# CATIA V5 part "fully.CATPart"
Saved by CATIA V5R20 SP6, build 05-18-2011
Part number: Gear_24_4H
Material "Gold Metal": density 7860 kg/m3, Young's modulus 2e+11 Pa, Poisson ratio 0.266
Bounding box of the stored display mesh (mm): x -23.5 to 23.5, y -125.239 to 125.239, z -125.245 to 125.245
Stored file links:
  E:\#01 CATIA Lecture Materials\#06 DMU\#11 DMU Page01 KIN EX11\fully.CATPart
  E:\06년 공학과제\CATIA File\Part2.CATPart
  C:\Program Files\Dassault Systemes\B20\win_b64\startup\materials\Catalog.CATMaterial
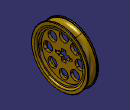
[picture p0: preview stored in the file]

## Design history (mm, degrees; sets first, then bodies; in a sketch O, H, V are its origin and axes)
Body1 (main body), material "Gold Metal"
  Sketch1, origin (0, 0, 0), H (0, 1, 0), V (0, 0, 1), geometry linked from another document
  Sketch2, origin (0, 0, 0), H (0, 1, 0), V (0, 0, 1), geometry linked from another document
  Sketch3, origin (0, 0, 0), H (0, -1, 0), V (0, 0, 1), geometry linked from another document
  Pad1: profile Sketch2, direction (1, 0, 0), length 18.5, mirrored extent
  Sketch4 on start face of Pad1, origin (-18.5, 0, 0), H (0, -1, 0), V (0, 0, 1)
    circle A1 centre (0, 0) radius 97.5
    radius A1 = 97.5
  Pocket1: profile Sketch4, direction (1, 0, 0), length 13
  Mirror1: of Pocket1, about yz-plane
  Sketch5 on end face of Pocket1, origin (-5.5, 0, 0), H (0, -1, 0), V (0, 0, 1)
  Pocket2: profile Sketch1, direction (-1, 0, 0), through (limit type 3), opposite side through (limit type 3)
  Body2
    Sketch6 on start face of Pad1, origin (-18.5, 0, 0), H (0, -1, 0), V (0, 0, 1)
      construction circle A1 centre (0, 0) radius 90
      construction circle A2 centre (0, 0) radius 50
      circle A3 centre (49.4975, 49.4975) radius 20
      axis line L1 (49.4975, 49.4975) -> (0, 0)
      radius A1 = 90
      radius A2 = 50
      angle L1 V = 45
      tangency: A3 A1, A3 A2
  Add1: tool Body2
  Pocket3: profile Sketch6, direction (-1, 0, 0), through (limit type 3)
  CircPattern1: of Pocket3, instances 8, angular step 45 {= 360.0*1 deg/CircPattern1.AngularNumber}, axis from face of Pad1
  Sketch7 on end face of Pocket1, origin (-5.5, 0, 0), H (0, -1, 0), V (0, 0, 1)
    line L1 (-36, 5) -> (36, 5)
    line L2 (36, 5) -> (36, -5)
    line L3 (36, -5) -> (-36, -5)
    line L4 (-36, -5) -> (-36, 5)
    distance V L2 = 36
    length L2 = 10
    horizontal: L1 H, L3 H
    vertical: L2 V, L4 V
    symmetry: L1 L3 H, L4 L2 V
  Pocket4: profile Sketch7, direction (1, 0, 0), through (limit type 3)
  Sketch8 on zx-plane, origin (0, 0, 0), H (-1, 0, 0), V (0, 0, 1)
    line L1 (-23.5, -111.2454) -> (-23.5, -123.2454)
    line L2 (-21.5, -125.2454) -> (-19.7031, -125.2454)
    line L3 (-17.7031, -123.2454) -> (-17.7031, -120.2807)
    point P1 (0, -108.2454)
    line L4 (-15.5, -103.2454) -> (0, -103.2454)
    point P2 (0, -103.2454)
    point P3 (0, -103.2454)
    line L5 (23.5, -111.2454) -> (23.5, -123.2454)
    line L6 (21.5, -125.2454) -> (19.7031, -125.2454)
    line L7 (17.7031, -123.2454) -> (17.7031, -120.2807)
    line L8 (15.5, -103.2454) -> (0, -103.2454)
    point P4 (0, -131.2454)
    reference intersected line E1 (-18.5, -107.5) -> (-18.5, 107.5) from end face of Pad1
    point P5 (-17.7031, -120.2807)
    point P6 (17.7031, -120.2807)
    arc A1 centre (15.5, -111.2454) radius 8 from (15.5, -103.2454) to (23.5, -111.2454) cw
    arc A2 centre (-15.5, -111.2454) radius 8 from (-15.5, -103.2454) to (-23.5, -111.2454) ccw
    arc A3 centre (-21.5, -123.2454) radius 2 from (-21.5, -125.2454) to (-23.5, -123.2454) cw
    arc A4 centre (-19.7031, -123.2454) radius 2 from (-19.7031, -125.2454) to (-17.7031, -123.2454) ccw
    arc A5 centre (19.7031, -123.2454) radius 2 from (17.7031, -123.2454) to (19.7031, -125.2454) ccw
    arc A6 centre (21.5, -123.2454) radius 2 from (23.5, -123.2454) to (21.5, -125.2454) cw
    axis line L9 (-60.4401, 0) -> (74.7022, 0)
    point P25 (-60.4401, 0)
    arc A7 centre (0, -127.2831) radius 19.0377 from (-17.7031, -120.2807) to (17.7031, -120.2807) cw
    point P28 (17.7031, -120.2807)
    distance L1 E1 = 5
    distance L4 H = 103.2454
    distance L6 L8 = 22
    distance P4 L8 = 28
    radius A1 = 8
    radius A2 = 8
    radius A3 = 2
    radius A4 = 2
    radius A5 = 2
    radius A6 = 2
    distance L3 L1 = 5.7969
    distance P2 P1 = 5
    length L7 = 2.9647
    vertical: L1 V, L3 V
    horizontal: L2 H, L4 H, L9 H
    coincidence: P1 V, P2 V, P4 V, P25 H, P2 P3, A7 P1, P28 L7, A7 P6
    symmetry: P2 P3 V, L1 L5 V, L2 L6 V, L3 L7 V, L4 L8 V, P6 P5 V
    tangency: A1 L8, A1 L5, A2 L4, A2 L1, A3 L2, A3 L1, A4 L2, A4 L3, A5 L7, A5 L6, A6 L5, A6 L6
  Shaft1: profile Sketch8, axis Sketch8.L9, angle 360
